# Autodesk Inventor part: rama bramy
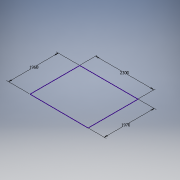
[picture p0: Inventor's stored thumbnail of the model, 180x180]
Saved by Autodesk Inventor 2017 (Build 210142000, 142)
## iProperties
Created: 2020-09
Part Number: rama bramy
Material: Generic
Document SubType Name: Modeling
Designer: X
Density: 1 g/cm^3
Appearance: Default
Author: X
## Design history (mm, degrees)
sketch "Szkic1"
  geometry: L1 (0, 0)-(0, 1960); L2 (0, 1960)-(2300, 1960); L3 (2300, 1960)-(2300, -10); L4 (0, 0)-(2300, -10)
  constraints: 8 end point, 2 vertical, 1 horizontal
  dimensions: "d6" = 1960 dimension on L1.start L1.end L1 L2.end L2 L3.end L3 L4; "d6" = 1960 distance of L1.start L1.end; "d7" = 2300 distance of L2.end L1.end; "d8" = 1970 distance of L3.end L2.end
